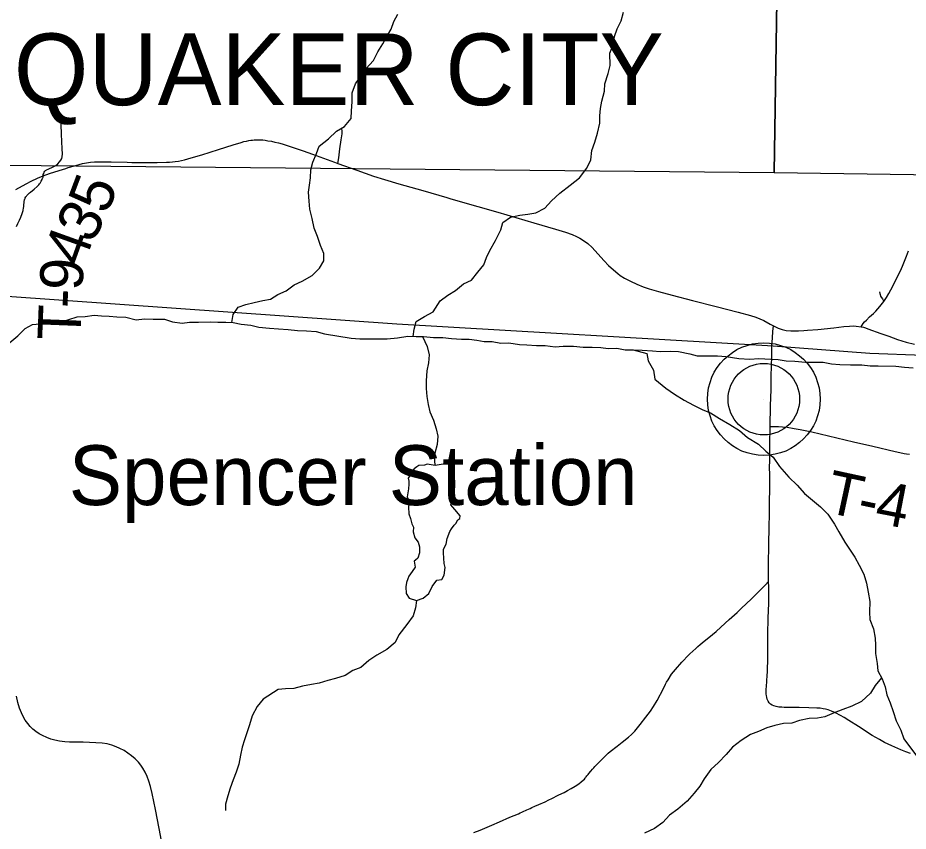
# Model space of a CAD drawing. Extents: x 0 to 34, y -8.9 to 22.
# Drawn here: x 25.767 to 26.944, y 12.069 to 13.144 of the extents above; entities that cross this region are included whole.
import ezdxf

# ---------------------------------------------------------------- set-up
doc = ezdxf.new("R2010")
doc.units = 0
for name, color, linetype in [('GM_X_Corporation', 7, 'Continuous'), ('GM_X_Corporation_Text', 7, 'Continuous'), ('GM_X_Minor_Lake', 7, 'Continuous'), ('GM_X_Minor_River', 7, 'Continuous'), ('GM_X_Rail_Line', 7, 'Continuous'), ('GM_X_State_Route', 7, 'Continuous'), ('GM_X_Township_Road', 7, 'Continuous'), ('GM_X_Township_Road_Text', 7, 'Continuous'), ('GM_X_Unincorporated', 7, 'Continuous'), ('GM_X_Unincorporated_Location', 7, 'Continuous'), ('GM_X_Unincorporated_Text', 7, 'Continuous')]:
    doc.layers.add(name, color=color, linetype=linetype)

msp = doc.modelspace()

# ---------------------------------------------------------------- linework, layer by layer
at = {"layer": 'GM_X_Corporation'}
for points in [[(26.7817, 13.904), (25.7664, 13.904), (25.7517, 12.949), (26.7664, 12.9392)], [(27.795, 13.904), (26.7817, 13.904), (26.7664, 12.9392), (27.7795, 12.9249)]]:
    msp.add_lwpolyline(points, close=True, dxfattribs=at)
at = {"layer": 'GM_X_Minor_Lake'}
for points in [[(26.3189, 12.5522), (26.3083, 12.554), (26.3045, 12.5528), (26.297, 12.5523), (26.2944, 12.5504), (26.291, 12.5477), (26.2884, 12.5446), (26.2861, 12.5401), (26.2832, 12.5355), (26.2839, 12.5317), (26.284, 12.5275), (26.2833, 12.5214), (26.2819, 12.5108), (26.2842, 12.5051), (26.2835, 12.4972), (26.284, 12.4884), (26.286, 12.482), (26.2879, 12.4752), (26.2899, 12.4707), (26.2895, 12.4646), (26.2919, 12.4567), (26.2961, 12.451), (26.2981, 12.4446), (26.2981, 12.437), (26.2959, 12.4298), (26.2926, 12.4271), (26.2911, 12.4259), (26.2923, 12.418), (26.2882, 12.4122), (26.2837, 12.4061), (26.2826, 12.4023), (26.2808, 12.3977), (26.2801, 12.392), (26.2805, 12.3829), (26.2844, 12.3769), (26.2942, 12.3736)], [(26.2942, 12.3736), (26.3029, 12.3767), (26.3104, 12.3829), (26.3149, 12.3924), (26.3208, 12.4005), (26.3276, 12.4017), (26.3306, 12.4074), (26.332, 12.4173), (26.3305, 12.4226), (26.3299, 12.437), (26.3295, 12.4416), (26.3332, 12.4481), (26.3347, 12.4557), (26.338, 12.4648), (26.3402, 12.4683), (26.3439, 12.4732), (26.3458, 12.4755), (26.3488, 12.4805), (26.3514, 12.4821), (26.3518, 12.4855), (26.3445, 12.4941), (26.3395, 12.5001), (26.3413, 12.5074), (26.3421, 12.5112), (26.3435, 12.5157), (26.3446, 12.5237), (26.3445, 12.5309), (26.344, 12.5385), (26.3428, 12.5449), (26.3428, 12.548), (26.3413, 12.5502), (26.3363, 12.5547), (26.3318, 12.5543), (26.3189, 12.5522)]]:
    msp.add_lwpolyline(points, dxfattribs=at)
at = {"layer": 'GM_X_Minor_River'}
for points in [[(26.0499, 12.7413), (26.0517, 12.7519), (26.0584, 12.7615), (26.0686, 12.765), (26.0795, 12.7678), (26.0912, 12.7702), (26.101, 12.7722), (26.1108, 12.778), (26.1217, 12.7831), (26.1323, 12.7908), (26.1428, 12.7959), (26.156, 12.8033), (26.1657, 12.8129), (26.1717, 12.8228), (26.1716, 12.8323), (26.1673, 12.8429), (26.1634, 12.855), (26.1587, 12.8659), (26.156, 12.8788), (26.1532, 12.8909), (26.152, 12.9015), (26.1515, 12.9132), (26.1525, 12.9227), (26.1539, 12.9322), (26.1546, 12.9429), (26.1571, 12.9531), (26.1619, 12.9646), (26.1656, 12.9741), (26.1776, 12.9837), (26.1885, 12.9941), (26.199, 13.0003), (26.2076, 13.0107), (26.2083, 13.0209), (26.2089, 13.0327), (26.2092, 13.0448), (26.2136, 13.0566), (26.227, 13.0765), (26.2371, 13.0873), (26.2431, 13.0987), (26.2494, 13.1094), (26.255, 13.119), (26.2606, 13.1289), (26.2642, 13.1388), (26.2694, 13.1488)], [(26.2897, 12.7228), (26.291, 12.7325), (26.2936, 12.7424), (26.3045, 12.7493), (26.3161, 12.7552), (26.3255, 12.7697), (26.3356, 12.7774), (26.3454, 12.7836), (26.3559, 12.7921), (26.3668, 12.7972), (26.375, 12.8075), (26.3829, 12.8175), (26.3866, 12.827), (26.391, 12.8365), (26.3984, 12.8495), (26.4055, 12.8636), (26.4081, 12.8732), (26.4182, 12.8805), (26.4307, 12.8829), (26.4409, 12.8842), (26.4518, 12.8862), (26.4635, 12.8921), (26.4725, 12.902), (26.4833, 12.912), (26.4972, 12.9228), (26.5093, 12.9325), (26.519, 12.9451), (26.5245, 12.9562), (26.5255, 12.9687), (26.5296, 12.9794), (26.5333, 12.9915), (26.5362, 13.0045), (26.5361, 13.0143), (26.5371, 13.0242), (26.5389, 13.0337), (26.5425, 13.0467), (26.5428, 13.0565), (26.5472, 13.0702), (26.5498, 13.0809), (26.5496, 13.0972), (26.5537, 13.1079), (26.5558, 13.1193), (26.5591, 13.1292), (26.5643, 13.1399), (26.5676, 13.1513)], [(25.7569, 12.7148), (25.7674, 12.7237), (25.7771, 12.7333), (25.7869, 12.7387), (25.8013, 12.7397), (25.813, 12.7409), (25.824, 12.7418), (25.8345, 12.745), (25.8458, 12.7486), (25.8561, 12.7491), (25.8681, 12.7507), (25.878, 12.7501), (25.8882, 12.7495), (25.8981, 12.7488), (25.9098, 12.7482), (25.9238, 12.7446), (25.9348, 12.7459), (25.9462, 12.7456), (25.9609, 12.7454), (25.9715, 12.7422), (25.9844, 12.7404), (25.9943, 12.7417), (26.006, 12.7415), (26.0219, 12.742), (26.0317, 12.7418), (26.0419, 12.7415), (26.0518, 12.7413), (26.0624, 12.7391), (26.0753, 12.7378), (26.0859, 12.7352), (26.0999, 12.7339), (26.1116, 12.7329), (26.1245, 12.7319), (26.1366, 12.7306), (26.1488, 12.7303), (26.1616, 12.7294), (26.1723, 12.7261), (26.2079, 12.7204), (26.2192, 12.7198), (26.2325, 12.7196), (26.2446, 12.7194), (26.2552, 12.7195), (26.2688, 12.7208), (26.2824, 12.7233), (26.2934, 12.7226), (26.3032, 12.7228), (26.3165, 12.7214), (26.3286, 12.7212), (26.3403, 12.7202), (26.3536, 12.7192), (26.3634, 12.719), (26.3737, 12.7179), (26.3835, 12.7162), (26.3941, 12.7159), (26.4055, 12.7138), (26.4161, 12.7143), (26.4301, 12.7122), (26.4399, 12.7116), (26.4524, 12.711), (26.4638, 12.7107), (26.4774, 12.709), (26.488, 12.7099), (26.5016, 12.7097), (26.5141, 12.7087), (26.5262, 12.7085), (26.5376, 12.7082), (26.5471, 12.7068), (26.5588, 12.7073), (26.5698, 12.7052), (26.5804, 12.7049)], [(26.3021, 12.7227), (26.3079, 12.7095), (26.3107, 12.6986), (26.31, 12.6879), (26.3078, 12.6773), (26.3068, 12.664), (26.3069, 12.6538), (26.3078, 12.6435), (26.3094, 12.6329), (26.3118, 12.6231), (26.3164, 12.6121), (26.32, 12.6008), (26.322, 12.591), (26.3213, 12.58), (26.3184, 12.5685), (26.3178, 12.5564), (26.3189, 12.5522)], [(26.5804, 12.7049), (26.5921, 12.7047), (26.6058, 12.7037), (26.616, 12.7027), (26.6292, 12.7033), (26.6402, 12.7027), (26.655, 12.6998), (26.6649, 12.6973), (26.6781, 12.697), (26.6917, 12.6972), (26.7031, 12.6962), (26.7198, 12.6938), (26.7345, 12.6928), (26.7463, 12.6937), (26.7622, 12.6928), (26.772, 12.6921), (26.7822, 12.6907), (26.794, 12.6901), (26.808, 12.6888), (26.8201, 12.6889), (26.8311, 12.6887), (26.8424, 12.6866), (26.8534, 12.6856), (26.8674, 12.6853), (26.8822, 12.6851), (26.8932, 12.6838), (26.9038, 12.6839), (26.9272, 12.6834), (26.9386, 12.682), (26.95, 12.6811)], [(26.5804, 12.7049), (26.5982, 12.7002), (26.6002, 12.6904), (26.6072, 12.6783), (26.6088, 12.6662), (26.6233, 12.6543), (26.6347, 12.6464), (26.6477, 12.6386), (26.6602, 12.632), (26.6724, 12.6257), (26.6823, 12.6216), (26.6944, 12.6145), (26.7078, 12.6064), (26.7207, 12.5986), (26.7314, 12.5892), (26.7459, 12.5803), (26.7554, 12.5713), (26.7653, 12.5631), (26.7734, 12.551), (26.786, 12.5368), (26.7971, 12.5263), (26.8067, 12.5154), (26.817, 12.5064), (26.8277, 12.4978), (26.8376, 12.4877), (26.8461, 12.4745), (26.8519, 12.4647), (26.8599, 12.4508), (26.873, 12.4312), (26.8788, 12.4207), (26.885, 12.4086), (26.8885, 12.3965), (26.8909, 12.3848), (26.8929, 12.3723), (26.8927, 12.3586), (26.8931, 12.3488), (26.8978, 12.3363), (26.8998, 12.3242), (26.9003, 12.3147), (26.9004, 12.3037), (26.9028, 12.2904), (26.9037, 12.281), (26.9091, 12.2704), (26.913, 12.2598), (26.9153, 12.2492), (26.9196, 12.2387), (26.9239, 12.227), (26.9278, 12.2149), (26.934, 12.2024), (26.9379, 12.1911), (26.9544, 12.1685)], [(26.2942, 12.3736), (26.2928, 12.3641), (26.2895, 12.3534), (26.2813, 12.3419), (26.2705, 12.3285), (26.2657, 12.3182), (26.2548, 12.309), (26.2416, 12.3016), (26.2311, 12.2943), (26.2206, 12.2854), (26.2097, 12.2811), (26.1999, 12.2745), (26.1871, 12.2706), (26.1769, 12.2682), (26.1655, 12.2646), (26.1553, 12.263), (26.1436, 12.2605), (26.1319, 12.2577), (26.121, 12.2572), (26.1111, 12.256), (26.0916, 12.2436), (26.0837, 12.2336), (26.0771, 12.2214), (26.0734, 12.2096), (26.0668, 12.1898), (26.0639, 12.1798), (26.0613, 12.1692), (26.0592, 12.1574), (26.0559, 12.1471), (26.0518, 12.1368), (26.0478, 12.1258), (26.0448, 12.1155), (26.0415, 12.1048), (26.0416, 12.0965)], [(26.9084, 12.2716), (26.9001, 12.2616), (26.8937, 12.2513), (26.8821, 12.2405), (26.8693, 12.2343), (26.8572, 12.2299), (26.8459, 12.2252), (26.8335, 12.2202), (26.8237, 12.2181), (26.8127, 12.218), (26.7999, 12.2152), (26.7901, 12.2116), (26.7791, 12.2111), (26.7674, 12.2087), (26.7568, 12.2055), (26.7459, 12.2005), (26.7354, 12.1969), (26.723, 12.1888), (26.7117, 12.1799), (26.7031, 12.1703), (26.693, 12.1596), (26.6828, 12.1504), (26.6739, 12.1381), (26.6683, 12.1286), (26.6608, 12.119), (26.6515, 12.1086), (26.6395, 12.0982), (26.6282, 12.0901), (26.6196, 12.0805), (26.6083, 12.0724), (26.5952, 12.0662)]]:
    msp.add_lwpolyline(points, dxfattribs=at)
at = {"layer": 'GM_X_Rail_Line'}
msp.add_lwpolyline([(23.7167, 13.1053), (23.7261, 13.1053), (24.5612, 13.0696), (25.0877, 13.0434), (25.1626, 13.0359), (25.2093, 13.0247), (25.2451, 13.0069), (25.2742, 12.991), (25.3139, 12.9634), (25.3815, 12.9092), (25.4453, 12.8521), (25.482, 12.8255), (25.5227, 12.8027), (25.5703, 12.7886), (25.6374, 12.7831), (25.7533, 12.7762), (26.268, 12.7393), (26.7653, 12.7104), (26.8928, 12.7005), (26.9639, 12.6979)], dxfattribs=at)
at = {"layer": 'GM_X_State_Route'}
for points in [[(25.7647, 12.9168), (25.7782, 12.9244), (25.7848, 12.9279), (25.7933, 12.9319), (25.8008, 12.935), (25.809, 12.9379), (25.822, 12.9421), (25.8308, 12.9449), (25.8338, 12.9458), (25.8438, 12.9488), (25.8529, 12.9511), (25.8581, 12.9523), (25.8633, 12.953), (25.8686, 12.9534), (25.8745, 12.9537), (25.8907, 12.9535), (25.9119, 12.9529), (25.9181, 12.9527), (25.9292, 12.9526), (25.9515, 12.9526), (25.9638, 12.9529), (25.9678, 12.9531), (25.9718, 12.9535), (25.9753, 12.9539), (25.9797, 12.9545), (25.9837, 12.9554), (25.9876, 12.9562), (25.9965, 12.9586), (26.0102, 12.9627), (26.0326, 12.97), (26.0516, 12.976), (26.0624, 12.9792), (26.0661, 12.9802), (26.0696, 12.981), (26.0723, 12.9815), (26.0752, 12.982), (26.0772, 12.9822), (26.0796, 12.9825), (26.0824, 12.9826), (26.0853, 12.9827), (26.0876, 12.9826), (26.0909, 12.9824), (26.094, 12.982), (26.0978, 12.9814), (26.1023, 12.9806), (26.1069, 12.9795), (26.1116, 12.9784), (26.1166, 12.9771), (26.1297, 12.9731), (26.1445, 12.9682), (26.1568, 12.9638), (26.1859, 12.9529), (26.19, 12.9514), (26.2151, 12.9424), (26.2374, 12.9345), (26.2516, 12.93), (26.2707, 12.9245), (26.3024, 12.9156), (26.334, 12.9063), (26.3393, 12.9047), (26.3752, 12.8945), (26.4015, 12.887), (26.4492, 12.873), (26.4778, 12.8646), (26.4909, 12.8605), (26.4997, 12.8573), (26.5055, 12.8548), (26.51, 12.8525), (26.5148, 12.8496), (26.5204, 12.8455), (26.5259, 12.8403), (26.5335, 12.8321), (26.5418, 12.8228), (26.5478, 12.8166), (26.5541, 12.8107), (26.5598, 12.806), (26.5633, 12.8035), (26.569, 12.7998), (26.5766, 12.7957), (26.585, 12.7918), (26.5936, 12.7883), (26.6012, 12.7857), (26.6136, 12.782), (26.6316, 12.7771), (26.6587, 12.7703), (26.6901, 12.7624), (26.7189, 12.7547), (26.7351, 12.7504), (26.7423, 12.7481), (26.7476, 12.7461), (26.7527, 12.7437), (26.7614, 12.7388), (26.7655, 12.7367)], [(26.7655, 12.7367), (26.7674, 12.7357), (26.7719, 12.7337), (26.7771, 12.7319), (26.7824, 12.7308), (26.7885, 12.7302), (26.7964, 12.7301), (26.7989, 12.7302), (26.8057, 12.7305), (26.8106, 12.7309), (26.8242, 12.732), (26.8452, 12.7343), (26.8588, 12.7359), (26.8663, 12.7365), (26.8713, 12.7366), (26.875, 12.7363), (26.8815, 12.7354)], [(26.8815, 12.7354), (26.8844, 12.7348), (26.8873, 12.734), (26.8905, 12.7329), (26.9075, 12.7268), (26.9179, 12.723), (26.9297, 12.7188), (26.941, 12.7153), (26.9519, 12.7126)], [(25.9573, 12.0562), (25.9541, 12.0726), (25.9493, 12.0977), (25.945, 12.1189), (25.9428, 12.1279), (25.9405, 12.135), (25.9381, 12.1413), (25.9355, 12.1468), (25.9324, 12.1522), (25.9297, 12.1562), (25.9266, 12.16), (25.9224, 12.1644), (25.9177, 12.1685), (25.9128, 12.1721), (25.9076, 12.1754), (25.9022, 12.1783), (25.8972, 12.1806), (25.8914, 12.1827), (25.8855, 12.1842), (25.8788, 12.1852), (25.8702, 12.1859), (25.8535, 12.1864), (25.8354, 12.1867), (25.8292, 12.1871), (25.8223, 12.1879), (25.8162, 12.1891), (25.8108, 12.1907), (25.8055, 12.1926), (25.7998, 12.1953), (25.7954, 12.1977), (25.7912, 12.2005), (25.7873, 12.2037), (25.7837, 12.2073), (25.7805, 12.2112), (25.7772, 12.2158), (25.7744, 12.2207), (25.7721, 12.2252), (25.7696, 12.2317), (25.7674, 12.2388), (25.7654, 12.2474)]]:
    msp.add_lwpolyline(points, dxfattribs=at)
at = {"layer": 'GM_X_Township_Road'}
for points in [[(25.8008, 12.935), (25.8009, 12.9366), (25.8015, 12.9383), (25.8023, 12.94), (25.803, 12.941), (25.8039, 12.942), (25.8046, 12.9426), (25.8053, 12.9431), (25.8073, 12.944), (25.8141, 12.9469), (25.8173, 12.9487), (25.8202, 12.951), (25.8224, 12.9533), (25.8242, 12.9557), (25.8253, 12.958), (25.8259, 12.9603), (25.8263, 12.964), (25.8261, 12.9708), (25.825, 12.99), (25.8245, 13.0029), (25.8239, 13.009), (25.8235, 13.0121), (25.8226, 13.0157), (25.8212, 13.0198), (25.8196, 13.0244), (25.8189, 13.0275)], [(26.19, 12.9514), (26.1912, 12.959), (26.1929, 12.9707), (26.1945, 12.9825), (26.1956, 12.9905), (26.1958, 12.9924), (26.1958, 12.9942), (26.1955, 12.9974), (26.1954, 12.998)], [(25.7657, 12.868), (25.7675, 12.8719), (25.7694, 12.8765), (25.7711, 12.8805), (25.7729, 12.8851), (25.7734, 12.8865), (25.7738, 12.8878), (25.7742, 12.889), (25.7744, 12.8901), (25.7748, 12.892), (25.7752, 12.895), (25.7754, 12.898), (25.7755, 12.8989), (25.7756, 12.9), (25.7757, 12.9011), (25.7759, 12.9021), (25.7761, 12.9029), (25.7763, 12.9036), (25.7765, 12.9043), (25.7768, 12.9051), (25.7772, 12.9061), (25.7779, 12.9072), (25.7786, 12.9083), (25.7794, 12.9092), (25.7799, 12.9098), (25.7804, 12.9102), (25.781, 12.9109), (25.7815, 12.9113), (25.7829, 12.9125), (25.7842, 12.9135), (25.7891, 12.9175), (25.7928, 12.9208), (25.7949, 12.923), (25.7959, 12.9243), (25.7967, 12.9255), (25.7982, 12.928), (25.7993, 12.9302), (25.8001, 12.9317), (25.8004, 12.9324), (25.8006, 12.9331), (25.8007, 12.934), (25.8008, 12.935)], [(26.9114, 12.7691), (26.9148, 12.7741), (26.918, 12.7794), (26.9232, 12.7893), (26.9269, 12.7965), (26.9308, 12.8043), (26.9347, 12.8127), (26.936, 12.8156), (26.9379, 12.8201), (26.9413, 12.8288), (26.9439, 12.8358)], [(26.9058, 12.7817), (26.9061, 12.7795), (26.9064, 12.7784), (26.9066, 12.7777), (26.9069, 12.777), (26.9072, 12.7762), (26.9079, 12.7748), (26.9095, 12.7723), (26.9114, 12.7691)], [(26.8815, 12.7354), (26.8842, 12.7397), (26.8861, 12.7421), (26.8884, 12.7443), (26.8927, 12.7485), (26.8977, 12.7531), (26.9007, 12.7562), (26.906, 12.7622), (26.9114, 12.7691)], [(26.7613, 12.6038), (26.7619, 12.6317), (26.7624, 12.6522), (26.7628, 12.6702), (26.763, 12.6833), (26.7633, 12.6969), (26.7636, 12.7099), (26.7642, 12.7211), (26.7649, 12.7292), (26.7655, 12.7367)], [(26.7655, 12.7367), (26.7674, 12.7357), (26.7719, 12.7337), (26.7771, 12.7319), (26.7824, 12.7308), (26.7885, 12.7302), (26.7964, 12.7301), (26.7989, 12.7302), (26.8057, 12.7305), (26.8106, 12.7309), (26.8242, 12.732), (26.8452, 12.7343), (26.8588, 12.7359), (26.8663, 12.7365), (26.8713, 12.7366), (26.875, 12.7363), (26.8815, 12.7354)], [(26.7591, 12.3989), (26.759, 12.4108), (26.7592, 12.4294), (26.7594, 12.44), (26.7597, 12.4524), (26.7601, 12.4666), (26.7601, 12.4723), (26.7603, 12.4865), (26.7605, 12.4952), (26.7605, 12.5033), (26.7606, 12.5082), (26.7607, 12.5174), (26.7608, 12.5205), (26.7608, 12.5242), (26.7608, 12.5337), (26.7609, 12.5399), (26.7606, 12.5498), (26.7609, 12.5585), (26.761, 12.5678), (26.7609, 12.579), (26.7609, 12.5846), (26.7612, 12.5988), (26.7613, 12.6038)], [(26.7613, 12.6038), (26.7666, 12.6038), (26.7722, 12.6037), (26.7777, 12.6035), (26.7839, 12.6028), (26.7931, 12.6013), (26.801, 12.5998), (26.8162, 12.5965), (26.8713, 12.5836), (26.8967, 12.5778), (26.9264, 12.5708), (26.9326, 12.5694), (26.9385, 12.5682), (26.9415, 12.5676), (26.9452, 12.567)], [(26.3698, 12.0674), (26.378, 12.0704), (26.3934, 12.077), (26.4036, 12.0815), (26.4173, 12.0874), (26.4286, 12.0921), (26.4308, 12.0931), (26.433, 12.0941), (26.4359, 12.0954), (26.4381, 12.0964), (26.4398, 12.0971), (26.442, 12.0981), (26.4443, 12.0991), (26.4466, 12.1001), (26.4505, 12.1019), (26.4555, 12.1041), (26.4638, 12.1079), (26.4687, 12.1102), (26.473, 12.1123), (26.4814, 12.1165), (26.4859, 12.1186), (26.4892, 12.1202), (26.4937, 12.1226), (26.4983, 12.1253), (26.5037, 12.1285), (26.5085, 12.1317), (26.5117, 12.1341), (26.5143, 12.1365), (26.5158, 12.1379), (26.5167, 12.1389), (26.5174, 12.1399), (26.5182, 12.1407), (26.5191, 12.1419), (26.5199, 12.1429), (26.5207, 12.1439), (26.5218, 12.1453), (26.5244, 12.1484), (26.5267, 12.1511), (26.5283, 12.1526), (26.5298, 12.1544), (26.5323, 12.1571), (26.5354, 12.1601), (26.5388, 12.1637), (26.5441, 12.1689), (26.5473, 12.1719), (26.5501, 12.1743), (26.5593, 12.1815), (26.5657, 12.1865), (26.5739, 12.1931), (26.5781, 12.1968), (26.5823, 12.2013), (26.5895, 12.2098), (26.5972, 12.2196), (26.6031, 12.2275), (26.6072, 12.2338), (26.6119, 12.2418), (26.6202, 12.2576), (26.6229, 12.2632), (26.6244, 12.2659), (26.6263, 12.2691), (26.6311, 12.2763), (26.636, 12.2826), (26.6446, 12.2923), (26.6471, 12.295), (26.6513, 12.2995), (26.6553, 12.3034), (26.6629, 12.3104), (26.6657, 12.3129), (26.669, 12.3156), (26.6742, 12.3199), (26.6803, 12.325), (26.6898, 12.3329), (26.6963, 12.3386), (26.7072, 12.3486), (26.7175, 12.3581), (26.7234, 12.3635), (26.7297, 12.3694), (26.7364, 12.3758), (26.7447, 12.384), (26.7502, 12.3898), (26.7546, 12.3942), (26.7591, 12.3989)], [(26.9466, 12.1717), (26.9407, 12.1736), (26.9338, 12.1764), (26.9219, 12.1817), (26.9124, 12.1863), (26.9058, 12.1899), (26.8962, 12.1955), (26.8778, 12.2072), (26.8653, 12.2151), (26.8589, 12.2191), (26.8541, 12.2219), (26.8475, 12.2253), (26.8424, 12.2275), (26.8377, 12.2291), (26.8343, 12.2301), (26.8311, 12.2308), (26.8274, 12.2314), (26.8231, 12.2317), (26.8125, 12.232), (26.7995, 12.2322), (26.7846, 12.2324), (26.7796, 12.2325), (26.7765, 12.2327), (26.7728, 12.233), (26.7692, 12.2336), (26.7662, 12.2345), (26.7639, 12.2355), (26.7619, 12.2369), (26.7601, 12.2387), (26.7588, 12.2407), (26.7575, 12.2435), (26.7567, 12.2458), (26.7563, 12.2483), (26.7562, 12.2501), (26.7562, 12.252), (26.7561, 12.255), (26.7565, 12.2619), (26.7567, 12.2656), (26.7569, 12.2687), (26.7573, 12.2736), (26.7576, 12.2804), (26.7581, 12.2978), (26.7583, 12.3127), (26.7584, 12.3295), (26.7586, 12.3506), (26.7595, 12.3705), (26.7597, 12.3841), (26.7595, 12.3916), (26.7591, 12.3989)]]:
    msp.add_lwpolyline(points, dxfattribs=at)
at = {"layer": 'GM_X_Unincorporated'}
for radius in [0.0744, 0.0472]:
    msp.add_circle((26.7529, 12.6399), radius, dxfattribs=at)
at = {"layer": 'GM_X_Unincorporated_Location'}
msp.add_line((26.7529, 12.6399), (26.7529, 12.6399), dxfattribs=at)

# ---------------------------------------------------------------- texts
at = {"layer": 'GM_X_Corporation_Text'}
msp.add_text('QUAKER CITY', height=0.094697, rotation=0, dxfattribs=at).set_placement((25.7621, 13.0284))
at = {"layer": 'GM_X_Township_Road_Text'}
for s, rotation, p in [('5', 69.2873, (25.8854, 12.8828)), ('3', 60.7134, (25.8644, 12.8438)), ('4', 70.2419, (25.8536, 12.8132)), ('9', 86.7927, (25.8525, 12.7825)), ('-', 87.603, (25.8515, 12.7594)), ('T', 87.7794, (25.8499, 12.7169)), ('T', 347.8184, (26.8321, 12.491)), ('4', 349.0381, (26.8978, 12.4769)), ('-', 348.0133, (26.8739, 12.482))]:
    msp.add_text(s, height=0.0568, rotation=rotation, dxfattribs=at).set_placement(p)
at = {"layer": 'GM_X_Unincorporated_Text'}
msp.add_text('Spencer Station', height=0.078977, rotation=0, dxfattribs=at).set_placement((25.8346, 12.4999))

doc.saveas('drawing.dxf')
